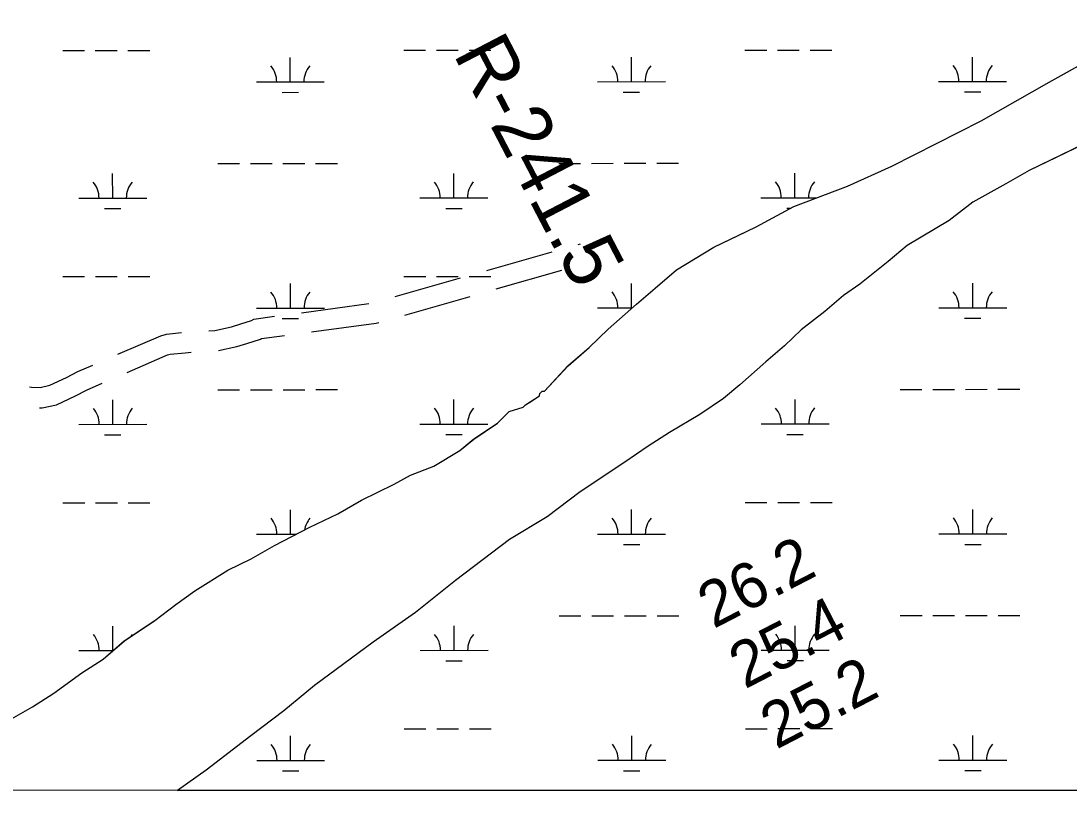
# Model space of a CAD drawing. Extents: x 3279314 to 3317160, y 734079 to 759431.
# Drawn here: x 3302113 to 3303655, y 739456 to 740597 of the extents above; entities that cross this region are included whole.
import ezdxf

# ---------------------------------------------------------------- set-up
doc = ezdxf.new("R2010")
doc.units = 0
for name, color, linetype in [('V-GRID-FRAM', 7, 'Continuous'), ('V-RIVR-RANG', 7, 'Continuous'), ('V-RIVR-RANG-IDEN', 7, 'Continuous'), ('V-ROAD-CNTR', 7, 'Continuous'), ('V-SITE-VEGE', 7, 'Continuous'), ('V-TOPO-SHOR', 7, 'Continuous'), ('V-WETL-SWMP', 7, 'Continuous')]:
    doc.layers.add(name, color=color, linetype=linetype)

msp = doc.modelspace()

# ---------------------------------------------------------------- linework, layer by layer
at = {"layer": 'V-GRID-FRAM'}
msp.add_lwpolyline([(3283455.7, 757641.4), (3314923.7, 757657.4), (3314940.9, 739471.9), (3283457, 739455.9), (3283455.7, 757641.4)], dxfattribs=at)
at = {"layer": 'V-ROAD-CNTR'}
for p, q in [((3302933.1, 740268.7), (3302936.3, 740269.6)), ((3302798.5, 740230.2), (3302894.7, 740257.7)), ((3302812.7, 740203.1), (3302908.9, 740230.6)), ((3302663.9, 740191.8), (3302760.1, 740219.3)), ((3302678.1, 740164.7), (3302774.3, 740192.1)), ((3302526.2, 740168.2), (3302625.3, 740181.5))]:
    msp.add_line(p, q, dxfattribs=at)
for points in [[(3302389.5, 740141.6), (3302398.5, 740142.2), (3302423.1, 740147.3), (3302436.9, 740151.8), (3302452.6, 740156.5), (3302456.1, 740158.9), (3302486.5, 740162.9)], [(3302540.7, 740139.9), (3302636.1, 740152.6), (3302639.7, 740153.7)], [(3302255.7, 740107), (3302319.1, 740134.4), (3302327.5, 740136.6), (3302349.6, 740139)], [(3302403.8, 740112.6), (3302430.8, 740118.3), (3302445.8, 740123.1), (3302465.7, 740129.1), (3302467.2, 740130.1), (3302501, 740134.6)], [(3302269.6, 740080.3), (3302329, 740106), (3302332.9, 740107.1), (3302354.9, 740109.3), (3302363.9, 740109.9)], [(3302126, 740059.1), (3302128.6, 740058.8), (3302141.8, 740058.4), (3302156, 740061.5), (3302180.4, 740072.9), (3302196.9, 740081.5), (3302219, 740091.1)], [(3302140.4, 740028.5), (3302144.6, 740028.4), (3302165.7, 740032.8), (3302193.7, 740046), (3302209.8, 740054.4), (3302232.8, 740064.4)]]:
    msp.add_lwpolyline(points, dxfattribs=at)
at = {"layer": 'V-SITE-VEGE'}
for points in [[(3302089, 739565), (3302130.4, 739588.3), (3302161.5, 739608.4), (3302203.1, 739638.6), (3302234.2, 739658.7), (3302265.4, 739685.6), (3302310.3, 739715.7), (3302341.4, 739739.2), (3302369.1, 739759.3), (3302417.5, 739789.4), (3302451.9, 739806), (3302486.5, 739826), (3302538.2, 739852.6), (3302579.6, 739872.5), (3302614.1, 739892.5), (3302662.3, 739915.8), (3302686.5, 739929.1), (3302720.9, 739942.3), (3302758.9, 739965.7), (3302779.7, 739982.5), (3302814.2, 740005.9), (3302831.6, 740022.7), (3302852.2, 740029.3), (3302855.7, 740032.6), (3302876.4, 740046), (3302876.5, 740049.4), (3302880, 740052.8), (3302883.4, 740052.8), (3302918.2, 740089.9), (3302949.4, 740116.8), (3302977.1, 740143.8), (3303018.8, 740180.8), (3303046.5, 740204.3), (3303077.7, 740231.2), (3303132.9, 740264.6), (3303195, 740294.5), (3303250.2, 740324.5), (3303329.3, 740354.1), (3303394.8, 740383.9), (3303525.8, 740450.4), (3303625.9, 740507.1), (3303691.5, 740543.7)], [(3303706.9, 740430.6), (3303596.6, 740377.5), (3303562.1, 740357.5), (3303513.8, 740330.8), (3303479.1, 740304), (3303417, 740267.2), (3303389.3, 740243.7), (3303347.7, 740210.1), (3303323.5, 740193.3), (3303295.8, 740169.8), (3303261.2, 740142.9), (3303236.8, 740119.4), (3303209.1, 740095.8), (3303171, 740062.2), (3303146.7, 740042), (3303112.1, 740018.6), (3303067.3, 739991.8), (3303036.2, 739971.8), (3303001.6, 739948.3), (3302935.9, 739904.8), (3302887.5, 739867.9), (3302832.2, 739834.5), (3302752.6, 739774.1), (3302693.7, 739727.1), (3302631.5, 739683.5), (3302545, 739619.8), (3302499.9, 739582.8), (3302451.5, 739545.9), (3302385.7, 739495.6), (3302343.4, 739465.5), (3303981.5, 739466.3)]]:
    msp.add_lwpolyline(points, dxfattribs=at)
at = {"layer": 'V-TOPO-SHOR'}
for points in [[(3302089, 739565), (3302130.4, 739588.3), (3302161.5, 739608.4), (3302203.1, 739638.6), (3302234.2, 739658.7), (3302265.4, 739685.6), (3302310.3, 739715.7), (3302341.4, 739739.2), (3302369.1, 739759.3), (3302417.5, 739789.4), (3302451.9, 739806), (3302486.5, 739826), (3302538.2, 739852.6), (3302579.6, 739872.5), (3302614.1, 739892.5), (3302662.3, 739915.8), (3302686.5, 739929.1), (3302720.9, 739942.3), (3302758.9, 739965.7), (3302779.7, 739982.5), (3302814.2, 740005.9), (3302821.2, 740012.6), (3302831.6, 740022.7), (3302852.2, 740029.3), (3302855.7, 740032.6), (3302866.1, 740039.3), (3302876.4, 740046), (3302876.5, 740049.4), (3302880, 740052.8), (3302883.4, 740052.8), (3302918.2, 740089.9), (3302949.4, 740116.8), (3302977.1, 740143.8), (3303018.8, 740180.8), (3303046.5, 740204.3), (3303077.7, 740231.2), (3303132.9, 740264.6), (3303167.4, 740281.2), (3303195, 740294.5), (3303250.2, 740324.5), (3303329.3, 740354.1), (3303394.8, 740383.9), (3303460.3, 740417.2), (3303525.8, 740450.4), (3303625.9, 740507.1), (3303691.5, 740543.7)], [(3303658.6, 740407.4), (3303596.6, 740377.5), (3303562.1, 740357.5), (3303513.8, 740330.8), (3303479.1, 740304), (3303417, 740267.2), (3303389.3, 740243.7), (3303347.7, 740210.1), (3303323.5, 740193.3), (3303295.8, 740169.8), (3303261.2, 740142.9), (3303236.8, 740119.4), (3303209.1, 740095.8), (3303171, 740062.2), (3303146.7, 740042), (3303112.1, 740018.6), (3303067.3, 739991.8), (3303036.2, 739971.8), (3303001.6, 739948.3), (3302935.9, 739904.8), (3302887.5, 739867.9), (3302832.2, 739834.5), (3302752.6, 739774.1), (3302693.7, 739727.1), (3302631.5, 739683.5), (3302545, 739619.8), (3302499.9, 739582.8), (3302451.5, 739545.9), (3302385.7, 739495.6), (3302343.4, 739465.5)]]:
    msp.add_lwpolyline(points, dxfattribs=at)
at = {"layer": 'V-WETL-SWMP'}
for p, q in [((3302174.7, 740553.9), (3302206.7, 740554)), ((3302222.7, 740554), (3302254.7, 740554)), ((3302270.7, 740554), (3302302.7, 740554)), ((3302676.6, 740554.2), (3302708.6, 740554.2)), ((3302724.6, 740554.2), (3302756.6, 740554.2)), ((3302772.6, 740554.2), (3302804.6, 740554.3)), ((3303178.5, 740554.5), (3303210.5, 740554.5)), ((3303226.5, 740554.5), (3303258.5, 740554.5)), ((3303274.5, 740554.5), (3303306.5, 740554.5)), ((3303513.4, 740508.2), (3303513.4, 740544.2)), ((3302509.6, 740507.7), (3302509.6, 740543.7)), ((3303011.5, 740507.9), (3303011.5, 740543.9)), ((3303625.9, 740507.1), (3303691.5, 740543.7)), ((3303625.9, 740507.1), (3303691.5, 740543.7)), ((3302459.6, 740507.7), (3302559.6, 740507.7)), ((3302961.5, 740507.9), (3303061.5, 740508)), ((3303463.4, 740508.2), (3303563.4, 740508.2)), ((3303525.8, 740450.4), (3303625.9, 740507.1)), ((3303525.8, 740450.4), (3303625.9, 740507.1)), ((3302497.6, 740492.2), (3302521.6, 740492.3)), ((3302999.5, 740492.5), (3303023.5, 740492.5)), ((3303501.4, 740492.8), (3303525.4, 740492.8)), ((3303394.8, 740383.9), (3303525.8, 740450.4)), ((3303394.8, 740383.9), (3303525.8, 740450.4)), ((3303706.9, 740430.6), (3303596.6, 740377.5)), ((3303706.9, 740430.6), (3303596.6, 740377.5)), ((3302402.8, 740387.6), (3302434.8, 740387.6)), ((3302450.8, 740387.6), (3302482.8, 740387.6)), ((3302498.8, 740387.6), (3302530.8, 740387.6)), ((3302546.8, 740387.6), (3302578.8, 740387.6)), ((3302904.7, 740387.8), (3302936.7, 740387.8)), ((3302952.7, 740387.8), (3302984.7, 740387.9)), ((3303000.7, 740387.9), (3303032.7, 740387.9)), ((3303048.7, 740387.9), (3303080.7, 740387.9)), ((3303329.3, 740354.1), (3303394.8, 740383.9)), ((3303329.3, 740354.1), (3303394.8, 740383.9)), ((3303596.6, 740377.5), (3303562.1, 740357.5)), ((3303596.6, 740377.5), (3303562.1, 740357.5)), ((3302248.3, 740336.7), (3302248.2, 740372.7)), ((3302750.2, 740337), (3302750.1, 740373)), ((3303252.1, 740337.2), (3303252, 740373.2)), ((3303250.2, 740324.5), (3303329.3, 740354.1)), ((3303250.2, 740324.5), (3303329.3, 740354.1)), ((3303562.1, 740357.5), (3303513.8, 740330.8)), ((3303562.1, 740357.5), (3303513.8, 740330.8)), ((3302198.3, 740336.7), (3302298.3, 740336.8)), ((3302700.2, 740337), (3302800.2, 740337)), ((3303202.1, 740337.2), (3303284.3, 740337.3)), ((3303513.8, 740330.8), (3303479.1, 740303.9)), ((3303513.8, 740330.8), (3303479.1, 740303.9)), ((3302236.3, 740321.3), (3302260.3, 740321.3)), ((3302738.2, 740321.6), (3302762.2, 740321.6)), ((3303195, 740294.5), (3303250.2, 740324.5)), ((3303195, 740294.5), (3303250.2, 740324.5)), ((3303240.1, 740321.8), (3303245.3, 740321.8)), ((3303479.1, 740303.9), (3303417, 740267.2)), ((3303479.1, 740303.9), (3303417, 740267.2)), ((3303132.9, 740264.6), (3303195, 740294.5)), ((3303132.9, 740264.6), (3303195, 740294.5)), ((3303417, 740267.2), (3303389.3, 740243.7)), ((3303417, 740267.2), (3303389.3, 740243.7)), ((3303077.7, 740231.2), (3303132.9, 740264.6)), ((3303077.7, 740231.2), (3303132.9, 740264.6)), ((3303389.3, 740243.7), (3303347.7, 740210.1)), ((3303389.3, 740243.7), (3303347.7, 740210.1)), ((3302174.9, 740221.3), (3302206.9, 740221.3)), ((3302222.9, 740221.3), (3302254.9, 740221.3)), ((3302270.9, 740221.3), (3302302.9, 740221.3)), ((3302676.8, 740221.5), (3302708.8, 740221.5)), ((3302724.8, 740221.5), (3302756.8, 740221.6)), ((3302772.8, 740221.6), (3302804.8, 740221.6)), ((3303046.5, 740204.3), (3303077.7, 740231.2)), ((3303046.5, 740204.3), (3303077.7, 740231.2)), ((3302509.8, 740175), (3302509.8, 740211)), ((3303011.7, 740175.3), (3303011.7, 740211.3)), ((3303347.7, 740210.1), (3303323.5, 740193.3)), ((3303347.7, 740210.1), (3303323.5, 740193.3)), ((3303513.6, 740175.5), (3303513.6, 740211.5)), ((3303018.7, 740180.8), (3303046.5, 740204.3)), ((3303018.7, 740180.8), (3303046.5, 740204.3)), ((3303323.5, 740193.3), (3303295.8, 740169.8)), ((3303323.5, 740193.3), (3303295.8, 740169.8)), ((3302459.8, 740175), (3302559.8, 740175)), ((3302961.7, 740175.2), (3303012.5, 740175.3)), ((3302977.1, 740143.8), (3303018.7, 740180.8)), ((3302977.1, 740143.8), (3303018.7, 740180.8)), ((3303463.6, 740175.5), (3303563.6, 740175.5)), ((3302497.8, 740159.6), (3302521.8, 740159.6)), ((3303295.8, 740169.8), (3303261.1, 740142.9)), ((3303295.8, 740169.8), (3303261.1, 740142.9)), ((3303501.6, 740160.1), (3303525.6, 740160.1)), ((3302949.3, 740116.8), (3302977.1, 740143.8)), ((3302949.3, 740116.8), (3302977.1, 740143.8)), ((3303261.1, 740142.9), (3303236.8, 740119.4)), ((3303261.1, 740142.9), (3303236.8, 740119.4)), ((3302918.1, 740089.9), (3302949.3, 740116.8)), ((3302918.1, 740089.9), (3302949.3, 740116.8)), ((3303236.8, 740119.4), (3303209.1, 740095.8)), ((3303236.8, 740119.4), (3303209.1, 740095.8)), ((3302883.4, 740052.8), (3302918.1, 740089.9)), ((3302883.4, 740052.8), (3302918.1, 740089.9)), ((3303209.1, 740095.8), (3303171, 740062.2)), ((3303209.1, 740095.8), (3303171, 740062.2)), ((3302403, 740054.9), (3302435, 740054.9)), ((3302451, 740054.9), (3302483, 740054.9)), ((3302499, 740054.9), (3302531, 740054.9)), ((3302547, 740055), (3302579, 740055)), ((3302876.5, 740049.4), (3302880, 740052.8)), ((3302876.5, 740049.4), (3302880, 740052.8)), ((3302880, 740052.8), (3302883.4, 740052.8)), ((3302880, 740052.8), (3302883.4, 740052.8)), ((3303171, 740062.2), (3303146.7, 740042)), ((3303171, 740062.2), (3303146.7, 740042)), ((3303406.8, 740055.4), (3303438.8, 740055.4)), ((3303454.8, 740055.4), (3303486.8, 740055.4)), ((3303502.8, 740055.4), (3303534.8, 740055.5)), ((3303550.8, 740055.5), (3303582.8, 740055.5)), ((3302248.4, 740004.1), (3302248.4, 740040.1)), ((3302750.3, 740004.3), (3302750.3, 740040.3)), ((3302855.7, 740032.6), (3302876.4, 740046)), ((3302855.7, 740032.6), (3302876.4, 740046)), ((3302876.4, 740046), (3302876.5, 740049.4)), ((3302876.4, 740046), (3302876.5, 740049.4)), ((3303146.7, 740042), (3303112.1, 740018.6)), ((3303146.7, 740042), (3303112.1, 740018.6)), ((3303252.2, 740004.6), (3303252.2, 740040.6)), ((3302814.2, 740005.9), (3302831.6, 740022.7)), ((3302814.2, 740005.9), (3302831.6, 740022.7)), ((3302831.6, 740022.7), (3302852.2, 740029.3)), ((3302831.6, 740022.7), (3302852.2, 740029.3)), ((3302852.2, 740029.3), (3302855.7, 740032.6)), ((3302852.2, 740029.3), (3302855.7, 740032.6)), ((3302779.7, 739982.4), (3302814.2, 740005.9)), ((3302779.7, 739982.4), (3302814.2, 740005.9)), ((3303112.1, 740018.6), (3303067.3, 739991.8)), ((3303112.1, 740018.6), (3303067.3, 739991.8)), ((3303202.2, 740004.5), (3303302.2, 740004.6)), ((3302198.4, 740004), (3302298.4, 740004.1)), ((3302700.3, 740004.3), (3302800.3, 740004.3)), ((3303067.3, 739991.8), (3303036.2, 739971.8)), ((3303067.3, 739991.8), (3303036.2, 739971.8)), ((3303240.2, 739989.1), (3303264.2, 739989.1)), ((3302236.4, 739988.6), (3302260.4, 739988.6)), ((3302738.3, 739988.9), (3302762.3, 739988.9)), ((3302758.9, 739965.6), (3302779.7, 739982.4)), ((3302758.9, 739965.6), (3302779.7, 739982.4)), ((3302720.9, 739942.3), (3302758.9, 739965.6)), ((3302720.9, 739942.3), (3302758.9, 739965.6)), ((3303036.2, 739971.8), (3303001.6, 739948.3)), ((3303036.2, 739971.8), (3303001.6, 739948.3)), ((3303001.6, 739948.3), (3302935.9, 739904.8)), ((3303001.6, 739948.3), (3302935.9, 739904.8)), ((3302662.3, 739915.8), (3302686.5, 739929.1)), ((3302662.3, 739915.8), (3302686.5, 739929.1)), ((3302686.5, 739929.1), (3302720.9, 739942.3)), ((3302686.5, 739929.1), (3302720.9, 739942.3)), ((3302614.1, 739892.5), (3302662.3, 739915.8)), ((3302614.1, 739892.5), (3302662.3, 739915.8)), ((3302935.9, 739904.8), (3302887.5, 739867.9)), ((3302935.9, 739904.8), (3302887.5, 739867.9)), ((3302175.1, 739888.6), (3302207.1, 739888.6)), ((3302223.1, 739888.6), (3302255.1, 739888.6)), ((3302271.1, 739888.6), (3302303.1, 739888.7)), ((3302579.5, 739872.5), (3302614.1, 739892.5)), ((3302579.5, 739872.5), (3302614.1, 739892.5)), ((3303178.9, 739889.1), (3303210.9, 739889.1)), ((3303226.9, 739889.1), (3303258.9, 739889.1)), ((3303274.9, 739889.2), (3303306.9, 739889.2)), ((3302509.9, 739842.3), (3302509.9, 739878.3)), ((3302538.2, 739852.6), (3302579.5, 739872.5)), ((3302538.2, 739852.6), (3302579.5, 739872.5)), ((3302887.5, 739867.9), (3302832.2, 739834.5)), ((3302887.5, 739867.9), (3302832.2, 739834.5)), ((3303011.8, 739842.6), (3303011.8, 739878.6)), ((3303513.8, 739842.8), (3303513.7, 739878.8)), ((3302486.5, 739826), (3302538.2, 739852.6)), ((3302486.5, 739826), (3302538.2, 739852.6)), ((3302459.9, 739842.3), (3302518.2, 739842.3)), ((3302961.8, 739842.6), (3303061.8, 739842.6)), ((3303463.8, 739842.8), (3303563.8, 739842.9)), ((3302451.9, 739806), (3302486.5, 739826)), ((3302451.9, 739806), (3302486.5, 739826)), ((3302832.2, 739834.5), (3302752.6, 739774.1)), ((3302832.2, 739834.5), (3302752.6, 739774.1)), ((3302999.9, 739827.2), (3303023.9, 739827.2)), ((3303501.8, 739827.4), (3303525.8, 739827.4)), ((3302417.5, 739789.4), (3302451.9, 739806)), ((3302417.5, 739789.4), (3302451.9, 739806)), ((3302369.1, 739759.3), (3302417.5, 739789.4)), ((3302369.1, 739759.3), (3302417.5, 739789.4)), ((3302752.6, 739774.1), (3302693.7, 739727.1)), ((3302752.6, 739774.1), (3302693.7, 739727.1)), ((3302341.4, 739739.2), (3302369.1, 739759.3)), ((3302341.4, 739739.2), (3302369.1, 739759.3)), ((3302310.3, 739715.7), (3302341.4, 739739.2)), ((3302310.3, 739715.7), (3302341.4, 739739.2)), ((3302693.7, 739727.1), (3302631.5, 739683.5)), ((3302693.7, 739727.1), (3302631.5, 739683.5)), ((3302265.3, 739685.6), (3302310.3, 739715.7)), ((3302265.3, 739685.6), (3302310.3, 739715.7)), ((3302905.1, 739722.5), (3302937.1, 739722.5)), ((3302953.1, 739722.5), (3302985.1, 739722.5)), ((3303001.1, 739722.5), (3303033.1, 739722.5)), ((3303049.1, 739722.5), (3303081.1, 739722.6)), ((3303407, 739722.7), (3303439, 739722.7)), ((3303455, 739722.7), (3303487, 739722.8)), ((3303503, 739722.8), (3303535, 739722.8)), ((3303551, 739722.8), (3303583, 739722.8)), ((3302248.6, 739671.4), (3302248.6, 739707.4)), ((3302750.5, 739671.6), (3302750.5, 739707.6)), ((3303252.4, 739671.9), (3303252.4, 739707.9)), ((3302234.1, 739658.7), (3302265.3, 739685.6)), ((3302234.1, 739658.7), (3302265.3, 739685.6)), ((3302631.5, 739683.5), (3302545, 739619.8)), ((3302631.5, 739683.5), (3302545, 739619.8)), ((3302198.6, 739671.4), (3302248.9, 739671.4)), ((3302700.5, 739671.6), (3302800.5, 739671.7)), ((3303202.4, 739671.9), (3303302.4, 739671.9)), ((3302203.1, 739638.6), (3302234.1, 739658.7)), ((3302203.1, 739638.6), (3302234.1, 739658.7)), ((3302738.5, 739656.2), (3302762.5, 739656.2)), ((3303240.4, 739656.5), (3303264.4, 739656.5)), ((3302161.5, 739608.4), (3302203.1, 739638.6)), ((3302161.5, 739608.4), (3302203.1, 739638.6)), ((3302545, 739619.8), (3302499.9, 739582.8)), ((3302545, 739619.8), (3302499.9, 739582.8)), ((3302130.4, 739588.3), (3302161.5, 739608.4)), ((3302130.4, 739588.3), (3302161.5, 739608.4)), ((3302089, 739565), (3302130.4, 739588.3)), ((3302089, 739565), (3302130.4, 739588.3)), ((3302499.9, 739582.8), (3302451.5, 739545.9)), ((3302499.9, 739582.8), (3302451.5, 739545.9)), ((3302451.5, 739545.9), (3302385.7, 739495.6)), ((3302451.5, 739545.9), (3302385.7, 739495.6)), ((3302510.1, 739509.7), (3302510.1, 739545.7)), ((3302677.1, 739556.2), (3302709.1, 739556.2)), ((3302725.1, 739556.2), (3302757.1, 739556.2)), ((3302773.1, 739556.2), (3302805.1, 739556.2)), ((3303012, 739509.9), (3303012, 739545.9)), ((3303179.1, 739556.4), (3303211.1, 739556.4)), ((3303227.1, 739556.5), (3303259.1, 739556.5)), ((3303275.1, 739556.5), (3303307.1, 739556.5)), ((3303513.9, 739510.2), (3303513.9, 739546.2)), ((3302460.1, 739509.6), (3302560.1, 739509.7)), ((3302962, 739509.9), (3303062, 739509.9)), ((3303463.9, 739510.1), (3303563.9, 739510.2)), ((3302385.7, 739495.6), (3302343.4, 739465.5)), ((3302385.7, 739495.6), (3302343.4, 739465.5)), ((3302498.1, 739494.2), (3302522.1, 739494.2)), ((3303000, 739494.5), (3303024, 739494.5)), ((3303501.9, 739494.7), (3303525.9, 739494.7)), ((3302343.4, 739465.5), (3303981.5, 739466.3)), ((3302343.4, 739465.5), (3303981.5, 739466.3))]:
    msp.add_line(p, q, dxfattribs=at)
for centre, start, end in [((3302454.4, 740508.1), 359.2573, 40.801), ((3302564.8, 740508.2), 139.2573, 180.801), ((3302956.3, 740508.4), 359.2573, 40.801), ((3303066.7, 740508.4), 139.2573, 180.801), ((3303458.2, 740508.6), 359.2573, 40.801), ((3303568.7, 740508.7), 139.2573, 180.801), ((3302193, 740337.2), 359.2573, 40.801), ((3302303.5, 740337.2), 139.2573, 180.801), ((3302694.9, 740337.4), 359.2573, 40.801), ((3302805.4, 740337.5), 139.2573, 180.801), ((3303196.8, 740337.7), 359.2573, 40.801), ((3303307.3, 740337.8), 139.2573, 180.801), ((3302454.5, 740175.5), 359.2573, 40.801), ((3302565, 740175.5), 139.2573, 180.801), ((3302956.4, 740175.7), 359.2573, 40.801), ((3303458.3, 740176), 359.2573, 40.801), ((3303568.8, 740176), 139.2573, 180.801), ((3302193.2, 740004.5), 359.2573, 40.801), ((3302303.7, 740004.6), 139.2573, 180.801), ((3302695.1, 740004.8), 359.2573, 40.801), ((3302805.6, 740004.8), 139.2573, 180.801), ((3303197, 740005), 359.2573, 40.801), ((3303307.5, 740005.1), 139.2573, 180.801), ((3302454.7, 739842.8), 359.2573, 40.801), ((3302565.2, 739842.8), 139.2573, 170.5937), ((3302956.6, 739843), 359.2573, 40.801), ((3303067.1, 739843.1), 139.2573, 180.801), ((3303458.5, 739843.3), 359.2573, 40.801), ((3303569, 739843.3), 139.2573, 180.801), ((3302193.3, 739671.8), 359.2573, 40.801), ((3302303.8, 739671.9), 139.2573, 145.3579), ((3302695.3, 739672.1), 359.2573, 40.801), ((3302805.7, 739672.1), 139.2573, 180.801), ((3303197.2, 739672.3), 359.2573, 40.801), ((3303307.6, 739672.4), 139.2573, 180.801), ((3302454.9, 739510.1), 359.2573, 40.801), ((3302565.4, 739510.2), 139.2573, 180.801), ((3302956.8, 739510.4), 359.2573, 40.801), ((3303067.3, 739510.4), 139.2573, 180.801), ((3303458.7, 739510.6), 359.2573, 40.801), ((3303569.2, 739510.7), 139.2573, 180.801)]:
    msp.add_arc(centre, 35.2, start, end, dxfattribs=at)

# ---------------------------------------------------------------- texts
at = {"layer": 'V-RIVR-RANG'}
for s, p in [('26.2', (3303132.3, 739702.7)), ('25.4', (3303178.4, 739614)), ('25.2', (3303224.6, 739525.3))]:
    msp.add_text(s, height=67, rotation=27.3583, dxfattribs=at).set_placement(p)
at = {"layer": 'V-RIVR-RANG-IDEN'}
msp.add_text('R-241.5', height=83, rotation=297.4962, dxfattribs=at).set_placement((3302748.6, 740548.9))

doc.saveas('drawing.dxf')
